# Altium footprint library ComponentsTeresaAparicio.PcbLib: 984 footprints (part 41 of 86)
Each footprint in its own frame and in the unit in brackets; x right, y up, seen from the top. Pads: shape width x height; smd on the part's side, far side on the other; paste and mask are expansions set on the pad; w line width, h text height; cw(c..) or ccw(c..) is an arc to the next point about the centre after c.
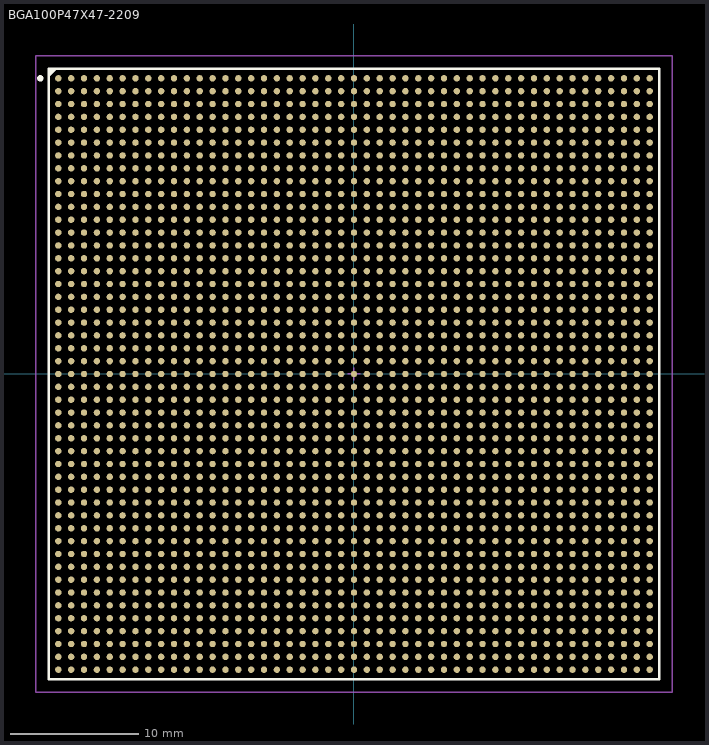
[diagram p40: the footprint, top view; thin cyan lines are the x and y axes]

## BGA100P47X47-2209 [mm] "BGA, 2209-Leads, Body 47.5x47.5mm, Pitch 1mm"
height 3.5
pads (2209):
  round 0.5 smd: A1(-23,23) A2(-22,23) A3(-21,23) A4(-20,23) A5(-19,23) A6(-18,23) A7(-17,23) A8(-16,23) A9(-15,23) A10(-14,23) A11(-13,23) A12(-12,23) A13(-11,23) A14(-10,23) A15(-9,23) A16(-8,23) A17(-7,23) A18(-6,23) A19(-5,23) A20(-4,23) A21(-3,23) A22(-2,23) A23(-1,23) A24(0,23) A25(1,23) A26(2,23) A27(3,23) A28(4,23) A29(5,23) A30(6,23) A31(7,23) A32(8,23) A33(9,23) A34(10,23) A35(11,23) A36(12,23) A37(13,23) A38(14,23) A39(15,23) A40(16,23) A41(17,23) A42(18,23) A43(19,23) A44(20,23) A45(21,23) A46(22,23) A47(23,23) AA1(-23,3) AA2(-22,3) AA3(-21,3) AA4(-20,3) AA5(-19,3) AA6(-18,3) AA7(-17,3) AA8(-16,3) AA9(-15,3) AA10(-14,3) AA11(-13,3) AA12(-12,3) AA13(-11,3) AA14(-10,3) AA15(-9,3) AA16(-8,3) AA17(-7,3) AA18(-6,3) AA19(-5,3) AA20(-4,3) AA21(-3,3) AA22(-2,3) AA23(-1,3) AA24(0,3) AA25(1,3) AA26(2,3) AA27(3,3) AA28(4,3) AA29(5,3) AA30(6,3) AA31(7,3) AA32(8,3) AA33(9,3) AA34(10,3) AA35(11,3) AA36(12,3) AA37(13,3) AA38(14,3) AA39(15,3) AA40(16,3) AA41(17,3) AA42(18,3) AA43(19,3) AA44(20,3) AA45(21,3) AA46(22,3) AA47(23,3) AB1(-23,2) AB2(-22,2) AB3(-21,2) AB4(-20,2) AB5(-19,2) AB6(-18,2) AB7(-17,2) AB8(-16,2) AB9(-15,2) AB10(-14,2) AB11(-13,2) AB12(-12,2) AB13(-11,2) AB14(-10,2) AB15(-9,2) AB16(-8,2) AB17(-7,2) AB18(-6,2) AB19(-5,2) AB20(-4,2) AB21(-3,2) AB22(-2,2) AB23(-1,2) AB24(0,2) AB25(1,2) AB26(2,2) AB27(3,2) AB28(4,2) AB29(5,2) AB30(6,2) AB31(7,2) AB32(8,2) AB33(9,2) AB34(10,2) AB35(11,2) AB36(12,2) AB37(13,2) AB38(14,2) AB39(15,2) AB40(16,2) AB41(17,2) AB42(18,2) AB43(19,2) AB44(20,2) AB45(21,2) AB46(22,2) AB47(23,2) AC1(-23,1) AC2(-22,1) AC3(-21,1) AC4(-20,1) AC5(-19,1) AC6(-18,1) AC7(-17,1) AC8(-16,1) AC9(-15,1) AC10(-14,1) AC11(-13,1) AC12(-12,1) AC13(-11,1) AC14(-10,1) AC15(-9,1) AC16(-8,1) AC17(-7,1) AC18(-6,1) AC19(-5,1) AC20(-4,1) AC21(-3,1) AC22(-2,1) AC23(-1,1) AC24(0,1) AC25(1,1) AC26(2,1) AC27(3,1) AC28(4,1) AC29(5,1) AC30(6,1) AC31(7,1) AC32(8,1) AC33(9,1) AC34(10,1) AC35(11,1) AC36(12,1) AC37(13,1) AC38(14,1) AC39(15,1) AC40(16,1) AC41(17,1) AC42(18,1) AC43(19,1) AC44(20,1) AC45(21,1) AC46(22,1) AC47(23,1) AD1(-23,0) AD2(-22,0) AD3(-21,0) AD4(-20,0) AD5(-19,0) AD6(-18,0) AD7(-17,0) AD8(-16,0) AD9(-15,0) AD10(-14,0) AD11(-13,0) AD12(-12,0) AD13(-11,0) AD14(-10,0) AD15(-9,0) AD16(-8,0) AD17(-7,0) AD18(-6,0) AD19(-5,0) AD20(-4,0) AD21(-3,0) AD22(-2,0) AD23(-1,0) AD24(0,0) AD25(1,0) AD26(2,0) AD27(3,0) AD28(4,0) AD29(5,0) AD30(6,0) AD31(7,0) AD32(8,0) AD33(9,0) AD34(10,0) AD35(11,0) AD36(12,0) AD37(13,0) AD38(14,0) AD39(15,0) AD40(16,0) AD41(17,0) AD42(18,0) AD43(19,0) AD44(20,0) AD45(21,0) AD46(22,0) AD47(23,0) AE1(-23,-1) AE2(-22,-1) AE3(-21,-1) AE4(-20,-1) AE5(-19,-1) AE6(-18,-1) AE7(-17,-1) AE8(-16,-1) AE9(-15,-1) AE10(-14,-1) AE11(-13,-1) AE12(-12,-1) AE13(-11,-1) AE14(-10,-1) AE15(-9,-1) AE16(-8,-1) AE17(-7,-1) AE18(-6,-1) AE19(-5,-1) AE20(-4,-1) AE21(-3,-1) AE22(-2,-1) AE23(-1,-1) AE24(0,-1) AE25(1,-1) AE26(2,-1) AE27(3,-1) AE28(4,-1) AE29(5,-1) AE30(6,-1) AE31(7,-1) AE32(8,-1) AE33(9,-1) AE34(10,-1) AE35(11,-1) AE36(12,-1) AE37(13,-1) AE38(14,-1) AE39(15,-1) AE40(16,-1) AE41(17,-1) AE42(18,-1) AE43(19,-1) AE44(20,-1) AE45(21,-1) AE46(22,-1) AE47(23,-1) AF1(-23,-2) AF2(-22,-2) AF3(-21,-2) AF4(-20,-2) AF5(-19,-2) AF6(-18,-2) AF7(-17,-2) AF8(-16,-2) AF9(-15,-2) AF10(-14,-2) AF11(-13,-2) AF12(-12,-2) AF13(-11,-2) AF14(-10,-2) AF15(-9,-2) AF16(-8,-2) AF17(-7,-2) AF18(-6,-2) AF19(-5,-2) AF20(-4,-2) AF21(-3,-2) AF22(-2,-2) AF23(-1,-2) AF24(0,-2) AF25(1,-2) AF26(2,-2) AF27(3,-2) AF28(4,-2) AF29(5,-2) AF30(6,-2) AF31(7,-2) AF32(8,-2) AF33(9,-2) AF34(10,-2) AF35(11,-2) AF36(12,-2) AF37(13,-2) AF38(14,-2) AF39(15,-2) AF40(16,-2) AF41(17,-2) AF42(18,-2) AF43(19,-2) AF44(20,-2) AF45(21,-2) AF46(22,-2) AF47(23,-2) AG1(-23,-3) AG2(-22,-3) AG3(-21,-3) AG4(-20,-3) AG5(-19,-3) AG6(-18,-3) AG7(-17,-3) AG8(-16,-3) AG9(-15,-3) AG10(-14,-3) AG11(-13,-3) AG12(-12,-3) AG13(-11,-3) AG14(-10,-3) AG15(-9,-3) AG16(-8,-3) AG17(-7,-3) AG18(-6,-3) AG19(-5,-3) AG20(-4,-3) AG21(-3,-3) AG22(-2,-3) AG23(-1,-3) AG24(0,-3) AG25(1,-3) AG26(2,-3) AG27(3,-3) AG28(4,-3) AG29(5,-3) AG30(6,-3) AG31(7,-3) AG32(8,-3) AG33(9,-3) AG34(10,-3) AG35(11,-3) AG36(12,-3) AG37(13,-3) AG38(14,-3) AG39(15,-3) AG40(16,-3) AG41(17,-3) AG42(18,-3) AG43(19,-3) AG44(20,-3) AG45(21,-3) AG46(22,-3) AG47(23,-3) AH1(-23,-4) AH2(-22,-4) AH3(-21,-4) AH4(-20,-4) AH5(-19,-4) AH6(-18,-4) AH7(-17,-4) AH8(-16,-4) AH9(-15,-4) AH10(-14,-4) AH11(-13,-4) AH12(-12,-4) AH13(-11,-4) AH14(-10,-4) AH15(-9,-4) AH16(-8,-4) AH17(-7,-4) AH18(-6,-4) AH19(-5,-4) AH20(-4,-4) AH21(-3,-4) AH22(-2,-4) AH23(-1,-4) AH24(0,-4) AH25(1,-4) AH26(2,-4) AH27(3,-4) AH28(4,-4) AH29(5,-4) AH30(6,-4) AH31(7,-4) AH32(8,-4) AH33(9,-4) AH34(10,-4) AH35(11,-4) AH36(12,-4) AH37(13,-4) AH38(14,-4) AH39(15,-4) AH40(16,-4) AH41(17,-4) AH42(18,-4) AH43(19,-4) AH44(20,-4) AH45(21,-4) AH46(22,-4) AH47(23,-4) AJ1(-23,-5) AJ2(-22,-5) AJ3(-21,-5) AJ4(-20,-5) AJ5(-19,-5) AJ6(-18,-5) AJ7(-17,-5) AJ8(-16,-5) AJ9(-15,-5) AJ10(-14,-5) AJ11(-13,-5) AJ12(-12,-5) AJ13(-11,-5) AJ14(-10,-5) AJ15(-9,-5) AJ16(-8,-5) AJ17(-7,-5) AJ18(-6,-5) AJ19(-5,-5) AJ20(-4,-5) AJ21(-3,-5) AJ22(-2,-5) AJ23(-1,-5) AJ24(0,-5) AJ25(1,-5) AJ26(2,-5) AJ27(3,-5) AJ28(4,-5) AJ29(5,-5) AJ30(6,-5) AJ31(7,-5) AJ32(8,-5) AJ33(9,-5) AJ34(10,-5) AJ35(11,-5) AJ36(12,-5) AJ37(13,-5) AJ38(14,-5) AJ39(15,-5) AJ40(16,-5) AJ41(17,-5) AJ42(18,-5) AJ43(19,-5) AJ44(20,-5) AJ45(21,-5) AJ46(22,-5) AJ47(23,-5) AK1(-23,-6) AK2(-22,-6) AK3(-21,-6) AK4(-20,-6) AK5(-19,-6) AK6(-18,-6) AK7(-17,-6) AK8(-16,-6) AK9(-15,-6) AK10(-14,-6) AK11(-13,-6) AK12(-12,-6) AK13(-11,-6) AK14(-10,-6) AK15(-9,-6) AK16(-8,-6) AK17(-7,-6) AK18(-6,-6) AK19(-5,-6) AK20(-4,-6) AK21(-3,-6) AK22(-2,-6) AK23(-1,-6) AK24(0,-6) AK25(1,-6) AK26(2,-6) AK27(3,-6) AK28(4,-6) AK29(5,-6) AK30(6,-6) AK31(7,-6) AK32(8,-6) AK33(9,-6) AK34(10,-6) AK35(11,-6) AK36(12,-6) AK37(13,-6) AK38(14,-6) AK39(15,-6) AK40(16,-6) AK41(17,-6) AK42(18,-6) AK43(19,-6) AK44(20,-6) AK45(21,-6) AK46(22,-6) AK47(23,-6) AL1(-23,-7) AL2(-22,-7) AL3(-21,-7) AL4(-20,-7) AL5(-19,-7) AL6(-18,-7) AL7(-17,-7) AL8(-16,-7) AL9(-15,-7) AL10(-14,-7) AL11(-13,-7) AL12(-12,-7) AL13(-11,-7) AL14(-10,-7) AL15(-9,-7) AL16(-8,-7) AL17(-7,-7) AL18(-6,-7) AL19(-5,-7) AL20(-4,-7) AL21(-3,-7) AL22(-2,-7) AL23(-1,-7) AL24(0,-7) AL25(1,-7) AL26(2,-7) AL27(3,-7) AL28(4,-7) AL29(5,-7) AL30(6,-7) AL31(7,-7) AL32(8,-7) AL33(9,-7) AL34(10,-7) AL35(11,-7) AL36(12,-7) AL37(13,-7) AL38(14,-7) AL39(15,-7) AL40(16,-7) AL41(17,-7) AL42(18,-7) AL43(19,-7) AL44(20,-7) AL45(21,-7) AL46(22,-7) AL47(23,-7) AM1(-23,-8) AM2(-22,-8) AM3(-21,-8) AM4(-20,-8) AM5(-19,-8) AM6(-18,-8) AM7(-17,-8) AM8(-16,-8) AM9(-15,-8) AM10(-14,-8) AM11(-13,-8) AM12(-12,-8) AM13(-11,-8) AM14(-10,-8) AM15(-9,-8) AM16(-8,-8) AM17(-7,-8) AM18(-6,-8) AM19(-5,-8) AM20(-4,-8) AM21(-3,-8) AM22(-2,-8) AM23(-1,-8) AM24(0,-8) AM25(1,-8) AM26(2,-8) AM27(3,-8) AM28(4,-8) AM29(5,-8) AM30(6,-8) AM31(7,-8) AM32(8,-8) AM33(9,-8) AM34(10,-8) AM35(11,-8) AM36(12,-8) AM37(13,-8) AM38(14,-8) AM39(15,-8) AM40(16,-8) AM41(17,-8) AM42(18,-8) AM43(19,-8) AM44(20,-8) AM45(21,-8) AM46(22,-8) AM47(23,-8) AN1(-23,-9) AN2(-22,-9) AN3(-21,-9) AN4(-20,-9) AN5(-19,-9) AN6(-18,-9) AN7(-17,-9) AN8(-16,-9) AN9(-15,-9) AN10(-14,-9) AN11(-13,-9) AN12(-12,-9) AN13(-11,-9) AN14(-10,-9) AN15(-9,-9) AN16(-8,-9) AN17(-7,-9) AN18(-6,-9) AN19(-5,-9) AN20(-4,-9) AN21(-3,-9) AN22(-2,-9) AN23(-1,-9) AN24(0,-9) AN25(1,-9) AN26(2,-9) AN27(3,-9) AN28(4,-9) AN29(5,-9) AN30(6,-9) AN31(7,-9) AN32(8,-9) AN33(9,-9) AN34(10,-9) AN35(11,-9) AN36(12,-9) AN37(13,-9) AN38(14,-9) AN39(15,-9) AN40(16,-9) AN41(17,-9) AN42(18,-9) AN43(19,-9) AN44(20,-9) AN45(21,-9) AN46(22,-9) AN47(23,-9) AP1(-23,-10) AP2(-22,-10) AP3(-21,-10) AP4(-20,-10) AP5(-19,-10) AP6(-18,-10) AP7(-17,-10) AP8(-16,-10) AP9(-15,-10) AP10(-14,-10) AP11(-13,-10) AP12(-12,-10) AP13(-11,-10) AP14(-10,-10) AP15(-9,-10) AP16(-8,-10) AP17(-7,-10) AP18(-6,-10) AP19(-5,-10) AP20(-4,-10) AP21(-3,-10) AP22(-2,-10) AP23(-1,-10) AP24(0,-10) AP25(1,-10) AP26(2,-10) AP27(3,-10) AP28(4,-10) AP29(5,-10) AP30(6,-10) AP31(7,-10) AP32(8,-10) AP33(9,-10) AP34(10,-10) AP35(11,-10) AP36(12,-10) AP37(13,-10) AP38(14,-10) AP39(15,-10) AP40(16,-10) AP41(17,-10) AP42(18,-10) AP43(19,-10) AP44(20,-10) AP45(21,-10) AP46(22,-10) AP47(23,-10) AR1(-23,-11) AR2(-22,-11) AR3(-21,-11) AR4(-20,-11) AR5(-19,-11) AR6(-18,-11) AR7(-17,-11) AR8(-16,-11) AR9(-15,-11) AR10(-14,-11) AR11(-13,-11) AR12(-12,-11) AR13(-11,-11) AR14(-10,-11) AR15(-9,-11) AR16(-8,-11) AR17(-7,-11) AR18(-6,-11) AR19(-5,-11) AR20(-4,-11) AR21(-3,-11) AR22(-2,-11) AR23(-1,-11) AR24(0,-11) AR25(1,-11) AR26(2,-11) AR27(3,-11) AR28(4,-11) AR29(5,-11) AR30(6,-11) AR31(7,-11) AR32(8,-11) AR33(9,-11) AR34(10,-11) AR35(11,-11) AR36(12,-11) AR37(13,-11) AR38(14,-11) AR39(15,-11) AR40(16,-11) AR41(17,-11) AR42(18,-11) AR43(19,-11) AR44(20,-11) AR45(21,-11) AR46(22,-11) AR47(23,-11) AT1(-23,-12) AT2(-22,-12) AT3(-21,-12) AT4(-20,-12) AT5(-19,-12) AT6(-18,-12) AT7(-17,-12) AT8(-16,-12) AT9(-15,-12) AT10(-14,-12) AT11(-13,-12) AT12(-12,-12) AT13(-11,-12) AT14(-10,-12) AT15(-9,-12) AT16(-8,-12) AT17(-7,-12) AT18(-6,-12) AT19(-5,-12) AT20(-4,-12) AT21(-3,-12) AT22(-2,-12) AT23(-1,-12) AT24(0,-12) AT25(1,-12) AT26(2,-12) AT27(3,-12) AT28(4,-12) AT29(5,-12) AT30(6,-12) AT31(7,-12) AT32(8,-12) AT33(9,-12) AT34(10,-12) AT35(11,-12) AT36(12,-12) AT37(13,-12) AT38(14,-12) AT39(15,-12) AT40(16,-12) AT41(17,-12) AT42(18,-12) AT43(19,-12) AT44(20,-12) AT45(21,-12) AT46(22,-12) AT47(23,-12) AU1(-23,-13) AU2(-22,-13) AU3(-21,-13) AU4(-20,-13) AU5(-19,-13) AU6(-18,-13) AU7(-17,-13) AU8(-16,-13) AU9(-15,-13) AU10(-14,-13) AU11(-13,-13) AU12(-12,-13) AU13(-11,-13) AU14(-10,-13) AU15(-9,-13) AU16(-8,-13) AU17(-7,-13) AU18(-6,-13) AU19(-5,-13) AU20(-4,-13) AU21(-3,-13) AU22(-2,-13) AU23(-1,-13) AU24(0,-13) AU25(1,-13) AU26(2,-13) AU27(3,-13) AU28(4,-13) AU29(5,-13) AU30(6,-13) AU31(7,-13) AU32(8,-13) AU33(9,-13) AU34(10,-13) AU35(11,-13) AU36(12,-13) AU37(13,-13) AU38(14,-13) AU39(15,-13) AU40(16,-13) AU41(17,-13) AU42(18,-13) AU43(19,-13) AU44(20,-13) AU45(21,-13) AU46(22,-13) AU47(23,-13) AV1(-23,-14) AV2(-22,-14) AV3(-21,-14) AV4(-20,-14) AV5(-19,-14) AV6(-18,-14) AV7(-17,-14) AV8(-16,-14) AV9(-15,-14) AV10(-14,-14) AV11(-13,-14) AV12(-12,-14) AV13(-11,-14) AV14(-10,-14) AV15(-9,-14) AV16(-8,-14) AV17(-7,-14) AV18(-6,-14) AV19(-5,-14) AV20(-4,-14) AV21(-3,-14) AV22(-2,-14) AV23(-1,-14) AV24(0,-14) AV25(1,-14) AV26(2,-14) AV27(3,-14) AV28(4,-14) AV29(5,-14) AV30(6,-14) AV31(7,-14) AV32(8,-14) AV33(9,-14) AV34(10,-14) AV35(11,-14) AV36(12,-14) AV37(13,-14) AV38(14,-14) AV39(15,-14) AV40(16,-14) AV41(17,-14) AV42(18,-14) AV43(19,-14) AV44(20,-14) AV45(21,-14) AV46(22,-14) AV47(23,-14) AW1(-23,-15) AW2(-22,-15) AW3(-21,-15) AW4(-20,-15) AW5(-19,-15) AW6(-18,-15) AW7(-17,-15) AW8(-16,-15) AW9(-15,-15) AW10(-14,-15) AW11(-13,-15) AW12(-12,-15) AW13(-11,-15) AW14(-10,-15) AW15(-9,-15) AW16(-8,-15) AW17(-7,-15) AW18(-6,-15) AW19(-5,-15) AW20(-4,-15) AW21(-3,-15) AW22(-2,-15) AW23(-1,-15) AW24(0,-15) AW25(1,-15) AW26(2,-15) AW27(3,-15) AW28(4,-15) AW29(5,-15) AW30(6,-15) AW31(7,-15) AW32(8,-15) AW33(9,-15) AW34(10,-15) AW35(11,-15) AW36(12,-15) AW37(13,-15) AW38(14,-15) AW39(15,-15) AW40(16,-15) AW41(17,-15) AW42(18,-15) AW43(19,-15) AW44(20,-15) AW45(21,-15) AW46(22,-15) AW47(23,-15) AY1(-23,-16) AY2(-22,-16) AY3(-21,-16) AY4(-20,-16) AY5(-19,-16) AY6(-18,-16) AY7(-17,-16) AY8(-16,-16) AY9(-15,-16) AY10(-14,-16) AY11(-13,-16) AY12(-12,-16) AY13(-11,-16) AY14(-10,-16) AY15(-9,-16) AY16(-8,-16) AY17(-7,-16) AY18(-6,-16) AY19(-5,-16) AY20(-4,-16) AY21(-3,-16) AY22(-2,-16) AY23(-1,-16) AY24(0,-16) AY25(1,-16) AY26(2,-16) AY27(3,-16) AY28(4,-16) AY29(5,-16) AY30(6,-16) AY31(7,-16) AY32(8,-16) AY33(9,-16) AY34(10,-16) AY35(11,-16) AY36(12,-16) AY37(13,-16) AY38(14,-16) AY39(15,-16) AY40(16,-16) AY41(17,-16) AY42(18,-16) AY43(19,-16) AY44(20,-16) AY45(21,-16) AY46(22,-16) AY47(23,-16) B1(-23,22) B2(-22,22) B3(-21,22) B4(-20,22) B5(-19,22) B6(-18,22) B7(-17,22) B8(-16,22) B9(-15,22) B10(-14,22) B11(-13,22) B12(-12,22) B13(-11,22) B14(-10,22) B15(-9,22) B16(-8,22) B17(-7,22) B18(-6,22) B19(-5,22) B20(-4,22) B21(-3,22) B22(-2,22) B23(-1,22) B24(0,22) B25(1,22) B26(2,22) B27(3,22) B28(4,22) B29(5,22) B30(6,22) B31(7,22) B32(8,22) B33(9,22) B34(10,22) B35(11,22) B36(12,22) B37(13,22) B38(14,22) B39(15,22) B40(16,22) B41(17,22) B42(18,22) B43(19,22) B44(20,22) B45(21,22) B46(22,22) B47(23,22) BA1(-23,-17) BA2(-22,-17) BA3(-21,-17) BA4(-20,-17) BA5(-19,-17) BA6(-18,-17) BA7(-17,-17) BA8(-16,-17) BA9(-15,-17) BA10(-14,-17) BA11(-13,-17) BA12(-12,-17) BA13(-11,-17) BA14(-10,-17) BA15(-9,-17) BA16(-8,-17) BA17(-7,-17) BA18(-6,-17) BA19(-5,-17) BA20(-4,-17) BA21(-3,-17) BA22(-2,-17) BA23(-1,-17) BA24(0,-17) BA25(1,-17) BA26(2,-17) BA27(3,-17) BA28(4,-17) BA29(5,-17) BA30(6,-17) BA31(7,-17) BA32(8,-17) BA33(9,-17) BA34(10,-17) BA35(11,-17) BA36(12,-17) BA37(13,-17) BA38(14,-17) BA39(15,-17) BA40(16,-17) BA41(17,-17) BA42(18,-17) BA43(19,-17) BA44(20,-17) BA45(21,-17) BA46(22,-17) BA47(23,-17) BB1(-23,-18) BB2(-22,-18) BB3(-21,-18) BB4(-20,-18) BB5(-19,-18) BB6(-18,-18) BB7(-17,-18) BB8(-16,-18) BB9(-15,-18) BB10(-14,-18) BB11(-13,-18) BB12(-12,-18) BB13(-11,-18) BB14(-10,-18) BB15(-9,-18) BB16(-8,-18) BB17(-7,-18) BB18(-6,-18) BB19(-5,-18) BB20(-4,-18) BB21(-3,-18) BB22(-2,-18) BB23(-1,-18) BB24(0,-18) BB25(1,-18) BB26(2,-18) BB27(3,-18) BB28(4,-18) BB29(5,-18) BB30(6,-18) BB31(7,-18) BB32(8,-18) BB33(9,-18) BB34(10,-18) BB35(11,-18) BB36(12,-18) BB37(13,-18) BB38(14,-18) BB39(15,-18) BB40(16,-18) BB41(17,-18) BB42(18,-18) BB43(19,-18) BB44(20,-18) BB45(21,-18) BB46(22,-18) BB47(23,-18) BC1(-23,-19) BC2(-22,-19) BC3(-21,-19) BC4(-20,-19) BC5(-19,-19) BC6(-18,-19) BC7(-17,-19) BC8(-16,-19) BC9(-15,-19) BC10(-14,-19) BC11(-13,-19) BC12(-12,-19) BC13(-11,-19) BC14(-10,-19) BC15(-9,-19) BC16(-8,-19) BC17(-7,-19) BC18(-6,-19) BC19(-5,-19) BC20(-4,-19) BC21(-3,-19) BC22(-2,-19) BC23(-1,-19) BC24(0,-19) BC25(1,-19) BC26(2,-19) BC27(3,-19) BC28(4,-19) BC29(5,-19) BC30(6,-19) BC31(7,-19) BC32(8,-19) BC33(9,-19) BC34(10,-19) BC35(11,-19) BC36(12,-19) BC37(13,-19) BC38(14,-19) BC39(15,-19) BC40(16,-19) BC41(17,-19) BC42(18,-19) BC43(19,-19) BC44(20,-19) BC45(21,-19) BC46(22,-19) BC47(23,-19) BD1(-23,-20) BD2(-22,-20) BD3(-21,-20) BD4(-20,-20) BD5(-19,-20) BD6(-18,-20) BD7(-17,-20) BD8(-16,-20) BD9(-15,-20) BD10(-14,-20) BD11(-13,-20) BD12(-12,-20) BD13(-11,-20) BD14(-10,-20) BD15(-9,-20) BD16(-8,-20) BD17(-7,-20) BD18(-6,-20) BD19(-5,-20) BD20(-4,-20) BD21(-3,-20) BD22(-2,-20) BD23(-1,-20) BD24(0,-20) BD25(1,-20) BD26(2,-20) BD27(3,-20) BD28(4,-20) BD29(5,-20) BD30(6,-20) BD31(7,-20) BD32(8,-20) BD33(9,-20) BD34(10,-20) BD35(11,-20) BD36(12,-20) BD37(13,-20) BD38(14,-20) BD39(15,-20) BD40(16,-20) BD41(17,-20) BD42(18,-20) BD43(19,-20) BD44(20,-20) BD45(21,-20) BD46(22,-20) BD47(23,-20) BE1(-23,-21) BE2(-22,-21) BE3(-21,-21) BE4(-20,-21) BE5(-19,-21) BE6(-18,-21) BE7(-17,-21) BE8(-16,-21) BE9(-15,-21) BE10(-14,-21) BE11(-13,-21) BE12(-12,-21) BE13(-11,-21) BE14(-10,-21) BE15(-9,-21) BE16(-8,-21) BE17(-7,-21) BE18(-6,-21) BE19(-5,-21) BE20(-4,-21) BE21(-3,-21) BE22(-2,-21) BE23(-1,-21) BE24(0,-21) BE25(1,-21) BE26(2,-21) BE27(3,-21) BE28(4,-21) BE29(5,-21) BE30(6,-21) BE31(7,-21) BE32(8,-21) BE33(9,-21) BE34(10,-21) BE35(11,-21) BE36(12,-21) BE37(13,-21) BE38(14,-21) BE39(15,-21) BE40(16,-21) BE41(17,-21) BE42(18,-21) BE43(19,-21) BE44(20,-21) BE45(21,-21) BE46(22,-21) BE47(23,-21) BF1(-23,-22) BF2(-22,-22) BF3(-21,-22) BF4(-20,-22) BF5(-19,-22) BF6(-18,-22) BF7(-17,-22) BF8(-16,-22) BF9(-15,-22) BF10(-14,-22) BF11(-13,-22) BF12(-12,-22) BF13(-11,-22) BF14(-10,-22) BF15(-9,-22) BF16(-8,-22) BF17(-7,-22) BF18(-6,-22) BF19(-5,-22) BF20(-4,-22) BF21(-3,-22) BF22(-2,-22) BF23(-1,-22) BF24(0,-22) BF25(1,-22) BF26(2,-22) BF27(3,-22) BF28(4,-22) BF29(5,-22) BF30(6,-22) BF31(7,-22) BF32(8,-22) BF33(9,-22) BF34(10,-22) BF35(11,-22) BF36(12,-22) BF37(13,-22) BF38(14,-22) BF39(15,-22) BF40(16,-22) BF41(17,-22) BF42(18,-22) BF43(19,-22) BF44(20,-22) BF45(21,-22) BF46(22,-22) BF47(23,-22) BG1(-23,-23) BG2(-22,-23) BG3(-21,-23) BG4(-20,-23) BG5(-19,-23) BG6(-18,-23) BG7(-17,-23) BG8(-16,-23) BG9(-15,-23) BG10(-14,-23) BG11(-13,-23) BG12(-12,-23) BG13(-11,-23) BG14(-10,-23) BG15(-9,-23) BG16(-8,-23) BG17(-7,-23) BG18(-6,-23) BG19(-5,-23) BG20(-4,-23) BG21(-3,-23) BG22(-2,-23) BG23(-1,-23) BG24(0,-23) BG25(1,-23) BG26(2,-23) BG27(3,-23) BG28(4,-23) BG29(5,-23) BG30(6,-23) BG31(7,-23) BG32(8,-23) BG33(9,-23) BG34(10,-23) BG35(11,-23) BG36(12,-23) BG37(13,-23) BG38(14,-23) BG39(15,-23) BG40(16,-23) BG41(17,-23) BG42(18,-23) BG43(19,-23) BG44(20,-23) BG45(21,-23) BG46(22,-23) BG47(23,-23) C1(-23,21) C2(-22,21) C3(-21,21) C4(-20,21) C5(-19,21) C6(-18,21) C7(-17,21) C8(-16,21) C9(-15,21) C10(-14,21) C11(-13,21) C12(-12,21) C13(-11,21) C14(-10,21) C15(-9,21) C16(-8,21) C17(-7,21) C18(-6,21) C19(-5,21) C20(-4,21) C21(-3,21) C22(-2,21) C23(-1,21) C24(0,21) C25(1,21) C26(2,21) C27(3,21) C28(4,21) C29(5,21) C30(6,21) C31(7,21) C32(8,21) C33(9,21) C34(10,21) C35(11,21) C36(12,21) C37(13,21) C38(14,21) C39(15,21) C40(16,21) C41(17,21) C42(18,21) C43(19,21) C44(20,21) C45(21,21) C46(22,21) C47(23,21) D1(-23,20) D2(-22,20) D3(-21,20) D4(-20,20) D5(-19,20) D6(-18,20) D7(-17,20) D8(-16,20) D9(-15,20) D10(-14,20) D11(-13,20) D12(-12,20) D13(-11,20) D14(-10,20) D15(-9,20) D16(-8,20) D17(-7,20) D18(-6,20) D19(-5,20) D20(-4,20) D21(-3,20) D22(-2,20) D23(-1,20) D24(0,20) D25(1,20) D26(2,20) D27(3,20) D28(4,20) D29(5,20) D30(6,20) D31(7,20) D32(8,20) D33(9,20) D34(10,20) D35(11,20) D36(12,20) D37(13,20) D38(14,20) D39(15,20) D40(16,20) D41(17,20) D42(18,20) D43(19,20) D44(20,20) D45(21,20) D46(22,20) D47(23,20) E1(-23,19) E2(-22,19) E3(-21,19) E4(-20,19) E5(-19,19) E6(-18,19) E7(-17,19) E8(-16,19) E9(-15,19) E10(-14,19) E11(-13,19) E12(-12,19) E13(-11,19) E14(-10,19) E15(-9,19) E16(-8,19) E17(-7,19) E18(-6,19) E19(-5,19) E20(-4,19) E21(-3,19) E22(-2,19) E23(-1,19) E24(0,19) E25(1,19) E26(2,19) E27(3,19) E28(4,19) E29(5,19) E30(6,19) E31(7,19) E32(8,19) E33(9,19) E34(10,19) E35(11,19) E36(12,19) E37(13,19) E38(14,19) E39(15,19) E40(16,19) E41(17,19) E42(18,19) E43(19,19) E44(20,19) E45(21,19) E46(22,19) E47(23,19) F1(-23,18) F2(-22,18) F3(-21,18) F4(-20,18) F5(-19,18) F6(-18,18) F7(-17,18) F8(-16,18) F9(-15,18) F10(-14,18) F11(-13,18) F12(-12,18) F13(-11,18) F14(-10,18) F15(-9,18) F16(-8,18) F17(-7,18) F18(-6,18) F19(-5,18) F20(-4,18) F21(-3,18) F22(-2,18) F23(-1,18) F24(0,18) F25(1,18) F26(2,18) F27(3,18) F28(4,18) F29(5,18) F30(6,18) F31(7,18) F32(8,18) F33(9,18) F34(10,18) F35(11,18) F36(12,18) F37(13,18) F38(14,18) F39(15,18) F40(16,18) F41(17,18) F42(18,18) F43(19,18) F44(20,18) F45(21,18) F46(22,18) F47(23,18) G1(-23,17) G2(-22,17) G3(-21,17) G4(-20,17) G5(-19,17) G6(-18,17) G7(-17,17) G8(-16,17) G9(-15,17) G10(-14,17) G11(-13,17) G12(-12,17) G13(-11,17) G14(-10,17) G15(-9,17) G16(-8,17) G17(-7,17) G18(-6,17) G19(-5,17) G20(-4,17) G21(-3,17) G22(-2,17) G23(-1,17) G24(0,17) G25(1,17) G26(2,17) G27(3,17) G28(4,17) G29(5,17) G30(6,17) G31(7,17) G32(8,17) G33(9,17) G34(10,17) G35(11,17) G36(12,17) G37(13,17) G38(14,17) G39(15,17) G40(16,17) G41(17,17) G42(18,17) G43(19,17) G44(20,17) G45(21,17) G46(22,17) G47(23,17) H1(-23,16) H2(-22,16) H3(-21,16) H4(-20,16) H5(-19,16) H6(-18,16) H7(-17,16) H8(-16,16) H9(-15,16) H10(-14,16) H11(-13,16) H12(-12,16) H13(-11,16) H14(-10,16) H15(-9,16) H16(-8,16) H17(-7,16) H18(-6,16) H19(-5,16) H20(-4,16) H21(-3,16) H22(-2,16) H23(-1,16) H24(0,16) H25(1,16) H26(2,16) H27(3,16) H28(4,16) H29(5,16) H30(6,16) H31(7,16) H32(8,16) H33(9,16) H34(10,16) H35(11,16) H36(12,16) H37(13,16) H38(14,16) H39(15,16) H40(16,16) H41(17,16) H42(18,16) H43(19,16) H44(20,16) H45(21,16) H46(22,16) H47(23,16) J1(-23,15) J2(-22,15) J3(-21,15) J4(-20,15) J5(-19,15) J6(-18,15) J7(-17,15) J8(-16,15) J9(-15,15) J10(-14,15) J11(-13,15) J12(-12,15) J13(-11,15) J14(-10,15) J15(-9,15) J16(-8,15) J17(-7,15) J18(-6,15) J19(-5,15) J20(-4,15) J21(-3,15) J22(-2,15) J23(-1,15) J24(0,15) J25(1,15) J26(2,15) J27(3,15) J28(4,15) J29(5,15) J30(6,15) J31(7,15) J32(8,15) J33(9,15) J34(10,15) J35(11,15) J36(12,15) J37(13,15) J38(14,15) J39(15,15) J40(16,15) J41(17,15) J42(18,15) J43(19,15) J44(20,15) J45(21,15) J46(22,15) J47(23,15) K1(-23,14) K2(-22,14) K3(-21,14) K4(-20,14) K5(-19,14) K6(-18,14) K7(-17,14) K8(-16,14) K9(-15,14) K10(-14,14) K11(-13,14) K12(-12,14) K13(-11,14) K14(-10,14) K15(-9,14) K16(-8,14) K17(-7,14) K18(-6,14) K19(-5,14) K20(-4,14) K21(-3,14) K22(-2,14) K23(-1,14) K24(0,14) K25(1,14) K26(2,14) K27(3,14) K28(4,14) K29(5,14) K30(6,14) K31(7,14) K32(8,14) K33(9,14) K34(10,14) K35(11,14) K36(12,14) K37(13,14) K38(14,14) K39(15,14) K40(16,14) K41(17,14) K42(18,14) K43(19,14) K44(20,14) K45(21,14) K46(22,14) K47(23,14) L1(-23,13) L2(-22,13) L3(-21,13) L4(-20,13) L5(-19,13) L6(-18,13) L7(-17,13) L8(-16,13) L9(-15,13) L10(-14,13) L11(-13,13) L12(-12,13) L13(-11,13) L14(-10,13) L15(-9,13) L16(-8,13) L17(-7,13) L18(-6,13) L19(-5,13) L20(-4,13) L21(-3,13) L22(-2,13) L23(-1,13) L24(0,13) L25(1,13) L26(2,13) L27(3,13) L28(4,13) L29(5,13) L30(6,13) L31(7,13) L32(8,13) L33(9,13) L34(10,13) L35(11,13) L36(12,13) L37(13,13) L38(14,13) L39(15,13) L40(16,13) L41(17,13) L42(18,13) L43(19,13) L44(20,13) L45(21,13) L46(22,13) L47(23,13) M1(-23,12) M2(-22,12) M3(-21,12) M4(-20,12) M5(-19,12) M6(-18,12) M7(-17,12) M8(-16,12) M9(-15,12) M10(-14,12) M11(-13,12) M12(-12,12) M13(-11,12) M14(-10,12) M15(-9,12) M16(-8,12) M17(-7,12) M18(-6,12) M19(-5,12) M20(-4,12) M21(-3,12) M22(-2,12) M23(-1,12) M24(0,12) M25(1,12) M26(2,12) M27(3,12) M28(4,12) M29(5,12) M30(6,12) M31(7,12) M32(8,12) M33(9,12) M34(10,12) M35(11,12) M36(12,12) M37(13,12) M38(14,12) M39(15,12) M40(16,12) M41(17,12) M42(18,12) M43(19,12) M44(20,12) M45(21,12) M46(22,12) M47(23,12) N1(-23,11) N2(-22,11) N3(-21,11) N4(-20,11) N5(-19,11) N6(-18,11) N7(-17,11) N8(-16,11) N9(-15,11) N10(-14,11) N11(-13,11) N12(-12,11) N13(-11,11) N14(-10,11) N15(-9,11) N16(-8,11) N17(-7,11) N18(-6,11) N19(-5,11) N20(-4,11) N21(-3,11) N22(-2,11) N23(-1,11) N24(0,11) N25(1,11) N26(2,11) N27(3,11) N28(4,11) N29(5,11) N30(6,11) N31(7,11) N32(8,11) N33(9,11) N34(10,11) N35(11,11) N36(12,11) N37(13,11) N38(14,11) N39(15,11) N40(16,11) N41(17,11) N42(18,11) N43(19,11) N44(20,11) N45(21,11) N46(22,11) N47(23,11) P1(-23,10) P2(-22,10) P3(-21,10) P4(-20,10) P5(-19,10) P6(-18,10) P7(-17,10) P8(-16,10) P9(-15,10) P10(-14,10) P11(-13,10) P12(-12,10) P13(-11,10) P14(-10,10) P15(-9,10) P16(-8,10) P17(-7,10) P18(-6,10) P19(-5,10) P20(-4,10) P21(-3,10) P22(-2,10) P23(-1,10) P24(0,10) P25(1,10) P26(2,10) P27(3,10) P28(4,10) P29(5,10) P30(6,10) P31(7,10) P32(8,10) P33(9,10) P34(10,10) P35(11,10) P36(12,10) P37(13,10) P38(14,10) P39(15,10) P40(16,10) P41(17,10) P42(18,10) P43(19,10) P44(20,10) P45(21,10) P46(22,10) P47(23,10) R1(-23,9) R2(-22,9) R3(-21,9) R4(-20,9) R5(-19,9) R6(-18,9) R7(-17,9) R8(-16,9) R9(-15,9) R10(-14,9) R11(-13,9) R12(-12,9) R13(-11,9) R14(-10,9) R15(-9,9) R16(-8,9) R17(-7,9) R18(-6,9) R19(-5,9) R20(-4,9) R21(-3,9) R22(-2,9) R23(-1,9) R24(0,9) R25(1,9) R26(2,9) R27(3,9) R28(4,9) R29(5,9) R30(6,9) R31(7,9) R32(8,9) R33(9,9) R34(10,9) R35(11,9) R36(12,9) R37(13,9) R38(14,9) R39(15,9) R40(16,9) R41(17,9) R42(18,9) R43(19,9) R44(20,9) R45(21,9) R46(22,9) R47(23,9) T1(-23,8) T2(-22,8) T3(-21,8) T4(-20,8) T5(-19,8) T6(-18,8) T7(-17,8) T8(-16,8) T9(-15,8) T10(-14,8) T11(-13,8) T12(-12,8) T13(-11,8) T14(-10,8) T15(-9,8) T16(-8,8) T17(-7,8) T18(-6,8) T19(-5,8) T20(-4,8) T21(-3,8) T22(-2,8) T23(-1,8) T24(0,8) T25(1,8) T26(2,8) T27(3,8) T28(4,8) T29(5,8) T30(6,8) T31(7,8) T32(8,8) T33(9,8) T34(10,8) T35(11,8) T36(12,8) T37(13,8) T38(14,8) T39(15,8) T40(16,8) T41(17,8) T42(18,8) T43(19,8) T44(20,8) T45(21,8) T46(22,8) T47(23,8) U1(-23,7) U2(-22,7) U3(-21,7) U4(-20,7) U5(-19,7) U6(-18,7) U7(-17,7) U8(-16,7) U9(-15,7) U10(-14,7) U11(-13,7) U12(-12,7) U13(-11,7) U14(-10,7) U15(-9,7) U16(-8,7) U17(-7,7) U18(-6,7) U19(-5,7) U20(-4,7) U21(-3,7) U22(-2,7) U23(-1,7) U24(0,7) U25(1,7) U26(2,7) U27(3,7) U28(4,7) U29(5,7) U30(6,7) U31(7,7) U32(8,7) U33(9,7) U34(10,7) U35(11,7) U36(12,7) U37(13,7) U38(14,7) U39(15,7) U40(16,7) U41(17,7) U42(18,7) U43(19,7) U44(20,7) U45(21,7) U46(22,7) U47(23,7) V1(-23,6) V2(-22,6) V3(-21,6) V4(-20,6) V5(-19,6) V6(-18,6) V7(-17,6) V8(-16,6) V9(-15,6) V10(-14,6) V11(-13,6) V12(-12,6) V13(-11,6) V14(-10,6) V15(-9,6) V16(-8,6) V17(-7,6) V18(-6,6) V19(-5,6) V20(-4,6) V21(-3,6) V22(-2,6) V23(-1,6) V24(0,6) V25(1,6) V26(2,6) V27(3,6) V28(4,6) V29(5,6) V30(6,6) V31(7,6) V32(8,6) V33(9,6) V34(10,6) V35(11,6) V36(12,6) V37(13,6) V38(14,6) V39(15,6) V40(16,6) V41(17,6) V42(18,6) V43(19,6) V44(20,6) V45(21,6) V46(22,6) V47(23,6) W1(-23,5) W2(-22,5) W3(-21,5) W4(-20,5) W5(-19,5) W6(-18,5) W7(-17,5) W8(-16,5) W9(-15,5) W10(-14,5) W11(-13,5) W12(-12,5) W13(-11,5) W14(-10,5) W15(-9,5) W16(-8,5) W17(-7,5) W18(-6,5) W19(-5,5) W20(-4,5) W21(-3,5) W22(-2,5) W23(-1,5) W24(0,5) W25(1,5) W26(2,5) W27(3,5) W28(4,5) W29(5,5) W30(6,5) W31(7,5) W32(8,5) W33(9,5) W34(10,5) W35(11,5) W36(12,5) W37(13,5) W38(14,5) W39(15,5) W40(16,5) W41(17,5) W42(18,5) W43(19,5) W44(20,5) W45(21,5) W46(22,5) W47(23,5) Y1(-23,4) Y2(-22,4) Y3(-21,4) Y4(-20,4) Y5(-19,4) Y6(-18,4) Y7(-17,4) Y8(-16,4) Y9(-15,4) Y10(-14,4) Y11(-13,4) Y12(-12,4) Y13(-11,4) Y14(-10,4) Y15(-9,4) Y16(-8,4) Y17(-7,4) Y18(-6,4) Y19(-5,4) Y20(-4,4) Y21(-3,4) Y22(-2,4) Y23(-1,4) Y24(0,4) Y25(1,4) Y26(2,4) Y27(3,4) Y28(4,4) Y29(5,4) Y30(6,4) Y31(7,4) Y32(8,4) Y33(9,4) Y34(10,4) Y35(11,4) Y36(12,4) Y37(13,4) Y38(14,4) Y39(15,4) Y40(16,4) Y41(17,4) Y42(18,4) Y43(19,4) Y44(20,4) Y45(21,4) Y46(22,4) Y47(23,4)
Top Overlay:
  circle w0.25: c-24.4,23 r0.125
  region: -23.169,23.75 -23.75,23.169 -23.75,23.75
  lines w0.2: -23.75,23.169 -23.169,23.75 ; -23.75,-23.75 23.75,-23.75 23.75,23.75 -23.75,23.75 -23.75,-23.75
Mechanical 13:
  lines w0.1: -23.75,-23.75 23.75,-23.75 23.75,23.75 -23.75,23.75 -23.75,-23.75
Mechanical 15:
  lines w0.1: -0.5,0 0.5,0 ; 0,-0.5 0,0.5 ; -24.75,-24.75 24.75,-24.75 24.75,24.75 -24.75,24.75 -24.75,-24.75
3D body: height 0, standoff 0, extent -23.75,-23.75 23.75,23.75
